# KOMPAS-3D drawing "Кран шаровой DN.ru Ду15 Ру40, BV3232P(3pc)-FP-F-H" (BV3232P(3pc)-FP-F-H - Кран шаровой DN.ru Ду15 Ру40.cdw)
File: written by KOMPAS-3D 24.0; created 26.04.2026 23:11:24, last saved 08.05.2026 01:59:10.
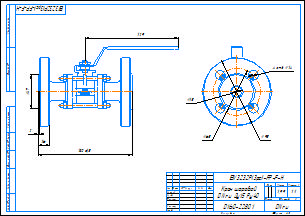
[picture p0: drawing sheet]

Document properties: Автор: Максим; Форматы листов документа: A3; Полное имя файла: BVxxP(3pc)-FP-F-H - Кран шаровой DN.ru Ду15 Ру40.cdw; Масса: 1.985; Наименование: Кран шаровой DN.ru Ду15 Ру40; Количество листов документа: 1; Примечание: D160-22801

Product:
- Body: Тело 1  | qty 1
    Масса: 2.156279
- Part/product: Кран шаровой DN.ru Ду15 Ру40  | designation BV3232P(3pc)-FP-F-H
    Масса: 1.985
    Раздел спецификации: Прочие изделия
    Форматы листов документа: A3
    Примечание: D160-22801

Views: Вид 1, Вид:1, Проекционный вид 2
Referenced files in D:\Rabota ebanaya\Апрель\BVxxP(3pc)-FP-F-H Кран шаровой Ду15-100\Исходники\DN15\: BVxxP(3pc)-FP-F-H - Кран шаровой DN.ru Ду15 Ру40.m3d, BVxxP(3pc)-FP-F-H - Кран шаровой DN.ru Ду15 Ру40.cdw
Referenced files in D:\Rabota ebanaya\Апрель\BV3232P(3pc)-FP-F-H Кран шаровой Ду15-100\Исходники\DN15\: BV3232P(3pc)-FP-F-H - Кран шаровой DN.ru Ду15 Ру40.m3d
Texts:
  Линейный размер
  BV3232P(3pc)-FP-F-H
  Диаметральный размер
  Кран шаровой
  DN.ru Ду15 Ру40
  Кран шаровой DN.ru Ду15 Ру40
  BV3232P(3pc)-FP-F-H Кран шаровой DN.ru Ду15 Ру40
Dimensions and other numbers on the sheet: 0; 3; 2; 4; 130±1,5; 16; 129; 47; 95; 65; 15; 4 отв.; 14; 1:1; 1; 1,99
